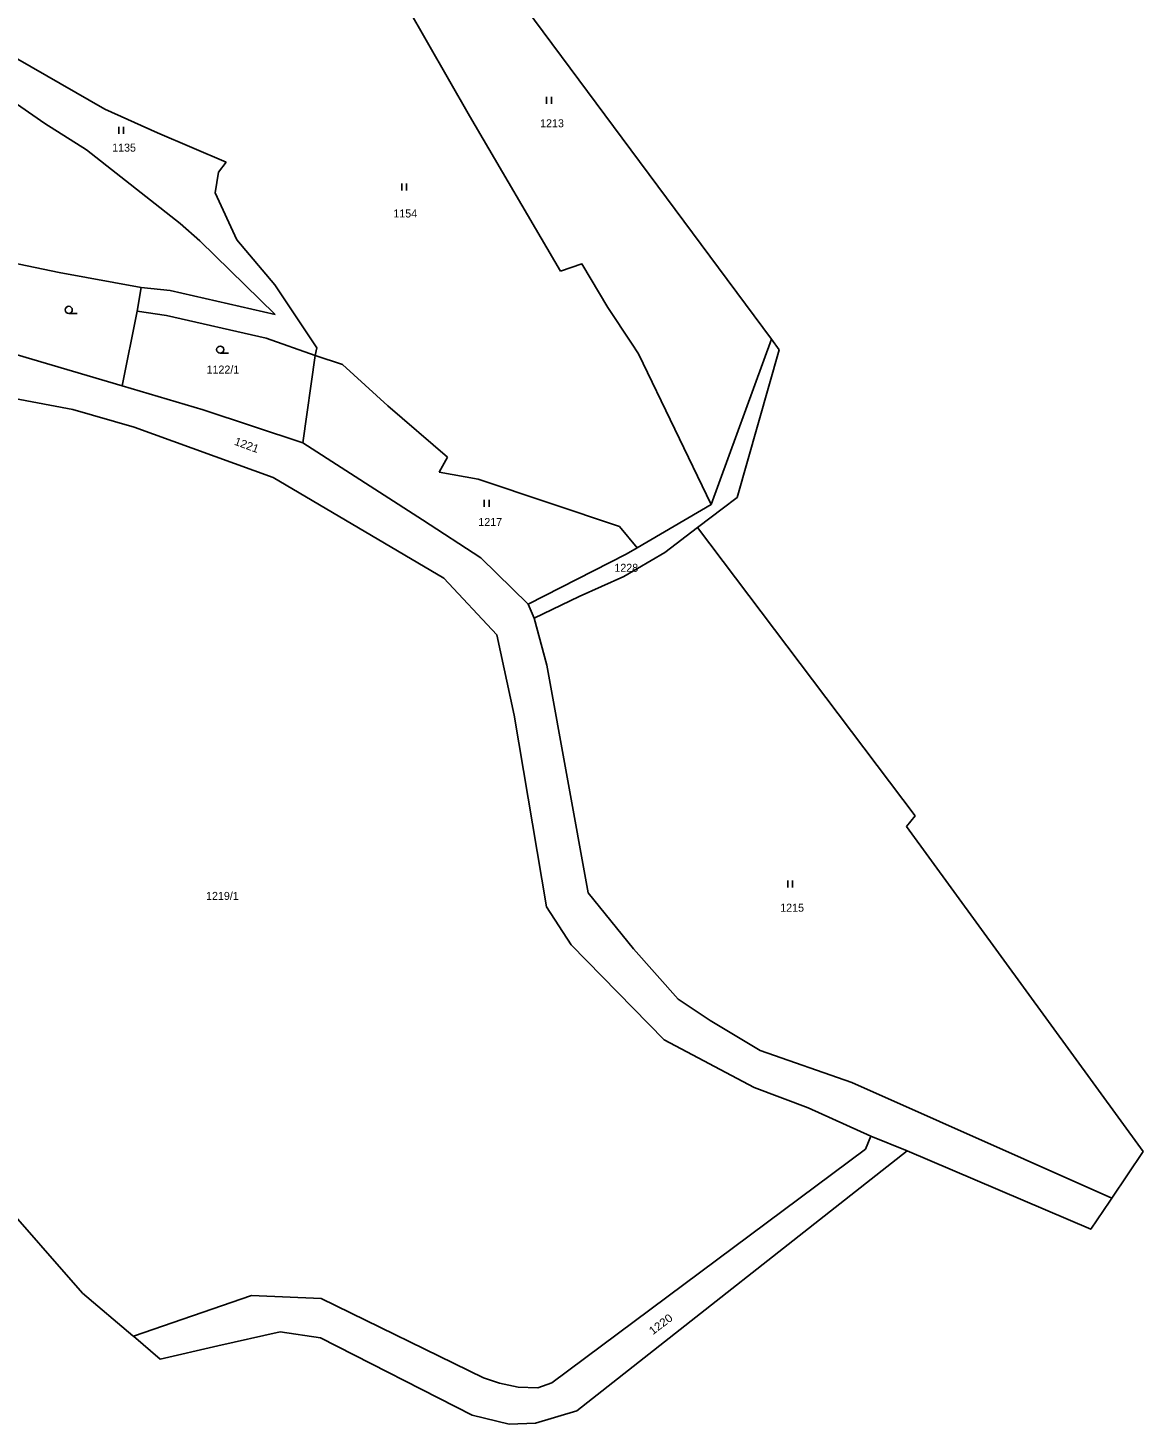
# Model space of a CAD drawing. Extents: x -744132 to -742433, y -984679 to -982287.
# Drawn here: x -742676.3 to -742439.3, y -983667 to -983370.4 of the extents above; entities that cross this region are included whole.
import ezdxf

# ---------------------------------------------------------------- set-up
doc = ezdxf.new("R2010")
doc.units = 0
doc.header["$LTSCALE"] = 0.68
doc.layers.add('1', color=7, linetype='Continuous', lineweight=25)
doc.layers.add('3', color=7, linetype='Continuous', lineweight=25)
doc.layers.add('2', color=7, linetype='Continuous')

msp = doc.modelspace()

# ---------------------------------------------------------------- linework, layer by layer
at = {"layer": '1'}
for p, q in [((-742608.33, -983315.24), (-742518.29, -983436.49)), ((-742595.81, -983365.68), (-742582.42, -983389.06)), ((-742681.79, -983375.07), (-742659.97, -983387.64)), ((-742672.71, -983390.65), (-742685.29, -983381.98)), ((-742659.97, -983387.64), (-742648.78, -983392.66)), ((-742582.42, -983389.06), (-742563.1, -983422.03)), ((-742663.86, -983396.26), (-742672.71, -983390.65)), ((-742648.78, -983392.66), (-742634.19, -983398.9)), ((-742643.96, -983411.94), (-742663.86, -983396.26)), ((-742634.19, -983398.9), (-742635.79, -983401.01)), ((-742635.79, -983401.01), (-742636.53, -983405.38)), ((-742636.53, -983405.38), (-742631.9, -983415.37)), ((-742639.78, -983415.64), (-742643.96, -983411.94)), ((-742623.76, -983431.28), (-742639.78, -983415.64)), ((-742631.9, -983415.37), (-742623.82, -983424.93)), ((-742681.58, -983419.83), (-742669.64, -983422.3)), ((-742669.64, -983422.3), (-742652.21, -983425.49)), ((-742652.21, -983425.49), (-742653.11, -983430.52)), ((-742652.21, -983425.49), (-742646.08, -983426.16)), ((-742646.08, -983426.16), (-742623.76, -983431.28)), ((-742623.82, -983424.93), (-742614.89, -983438.36)), ((-742653.11, -983430.52), (-742656.23, -983446.44)), ((-742653.11, -983430.52), (-742646.86, -983431.45)), ((-742553.08, -983429.77), (-742547.99, -983437.34)), ((-742646.86, -983431.45), (-742625.64, -983436.29)), ((-742625.64, -983436.29), (-742615.23, -983439.97)), ((-742531.12, -983471.6), (-742518.29, -983436.49)), ((-742516.61, -983438.75), (-742518.29, -983436.49)), ((-742683.09, -983438.48), (-742656.23, -983446.44)), ((-742614.89, -983438.36), (-742615.23, -983439.97)), ((-742547.99, -983437.34), (-742546.5, -983439.63)), ((-742525.53, -983470.1), (-742516.61, -983438.75)), ((-742617.9, -983458.53), (-742615.23, -983439.97)), ((-742615.23, -983439.97), (-742609.46, -983441.91)), ((-742609.46, -983441.91), (-742599.78, -983450.64)), ((-742546.5, -983439.63), (-742531.12, -983471.6)), ((-742691.68, -983446.7), (-742666.78, -983451.42)), ((-742656.23, -983446.44), (-742639.05, -983451.53)), ((-742599.78, -983450.64), (-742587.15, -983461.56)), ((-742666.78, -983451.42), (-742653.68, -983455.2)), ((-742639.05, -983451.53), (-742617.9, -983458.53)), ((-742653.68, -983455.2), (-742624.17, -983465.85)), ((-742592.46, -983474.85), (-742617.9, -983458.53)), ((-742587.15, -983461.56), (-742588.88, -983464.78)), ((-742624.17, -983465.85), (-742587.88, -983487.3)), ((-742588.88, -983464.78), (-742580.58, -983466.26)), ((-742580.58, -983466.26), (-742550.54, -983476.31)), ((-742531.12, -983471.6), (-742546.84, -983480.82)), ((-742528.73, -983472.52), (-742525.53, -983470.1)), ((-742580.04, -983482.94), (-742592.46, -983474.85)), ((-742533.98, -983476.47), (-742531.09, -983474.3)), ((-742531.09, -983474.3), (-742528.73, -983472.52)), ((-742550.54, -983476.31), (-742546.84, -983480.82)), ((-742533.98, -983476.47), (-742540.94, -983481.8)), ((-742487.72, -983537.78), (-742533.98, -983476.47)), ((-742549.18, -983482.19), (-742546.84, -983480.82)), ((-742569.98, -983492.78), (-742580.04, -983482.94)), ((-742569.98, -983492.78), (-742549.18, -983482.19)), ((-742540.94, -983481.8), (-742549.63, -983486.9)), ((-742549.63, -983486.9), (-742559.16, -983491.17)), ((-742587.88, -983487.3), (-742576.67, -983499.31)), ((-742569.98, -983492.78), (-742568.72, -983495.73)), ((-742559.16, -983491.17), (-742568.72, -983495.73)), ((-742568.72, -983495.73), (-742566.03, -983505.75)), ((-742576.67, -983499.31), (-742572.94, -983516.35)), ((-742566.03, -983505.75), (-742557.22, -983554.09)), ((-742572.94, -983516.35), (-742566.11, -983557.08)), ((-742489.59, -983540.03), (-742487.72, -983537.78)), ((-742439.29, -983609.05), (-742489.59, -983540.03)), ((-742557.22, -983554.09), (-742547.59, -983566.02)), ((-742566.11, -983557.08), (-742560.83, -983565.19)), ((-742560.83, -983565.19), (-742541.06, -983585.33)), ((-742547.59, -983566.02), (-742538.13, -983576.67)), ((-742538.13, -983576.67), (-742531.3, -983581.22)), ((-742531.3, -983581.22), (-742520.65, -983587.59)), ((-742541.06, -983585.33), (-742521.97, -983595.45)), ((-742520.65, -983587.59), (-742501.17, -983594.4)), ((-742521.97, -983595.45), (-742510.46, -983599.79)), ((-742501.17, -983594.4), (-742445.96, -983618.96)), ((-742510.46, -983599.79), (-742497.18, -983605.81)), ((-742498.32, -983608.54), (-742564.93, -983658.21)), ((-742497.18, -983605.81), (-742498.32, -983608.54)), ((-742497.18, -983605.81), (-742489.43, -983608.94)), ((-742559.66, -983664.16), (-742489.43, -983608.94)), ((-742445.96, -983618.96), (-742439.29, -983609.05)), ((-742683.1, -983618.19), (-742664.68, -983639.13)), ((-742446.38, -983619.59), (-742445.96, -983618.96)), ((-742664.68, -983639.13), (-742653.97, -983648.22)), ((-742628.75, -983639.68), (-742653.84, -983648.33)), ((-742614, -983640.27), (-742628.75, -983639.68)), ((-742579.44, -983657.18), (-742614, -983640.27)), ((-742653.97, -983648.22), (-742653.84, -983648.33)), ((-742653.84, -983648.33), (-742648.16, -983653.15)), ((-742635.96, -983650.35), (-742622.71, -983647.35)), ((-742622.71, -983647.35), (-742614.13, -983648.66)), ((-742614.13, -983648.66), (-742581.87, -983665.1)), ((-742648.16, -983653.15), (-742635.96, -983650.35)), ((-742576.06, -983658.3), (-742579.44, -983657.18)), ((-742572.07, -983659.12), (-742576.06, -983658.3)), ((-742564.93, -983658.21), (-742567.95, -983659.3)), ((-742567.95, -983659.3), (-742572.07, -983659.12)), ((-742568.43, -983666.78), (-742559.66, -983664.16)), ((-742581.87, -983665.1), (-742574.03, -983666.97)), ((-742574.03, -983666.97), (-742568.43, -983666.78))]:
    msp.add_line(p, q, dxfattribs=at)
for points in [[(-742563.1, -983422.03), (-742558.57, -983420.5), (-742553.08, -983429.77)], [(-742489.43, -983608.94), (-742450.42, -983625.59), (-742446.38, -983619.59)]]:
    msp.add_lwpolyline(points, dxfattribs=at)
at = {"layer": '3'}
for p, q in [((-742566.051, -983386.51), (-742566.051, -983385.01)), ((-742565.05, -983386.51), (-742565.05, -983385.01)), ((-742656.961, -983392.89), (-742656.961, -983391.39)), ((-742655.96, -983392.89), (-742655.96, -983391.39)), ((-742596.861, -983404.94), (-742596.861, -983403.44)), ((-742595.86, -983404.94), (-742595.86, -983403.44)), ((-742667.613, -983431.02), (-742665.863, -983431.02)), ((-742635.433, -983439.47), (-742633.683, -983439.47)), ((-742579.301, -983472.1), (-742579.301, -983470.6)), ((-742578.3, -983472.1), (-742578.3, -983470.6)), ((-742514.821, -983552.98), (-742514.821, -983551.48)), ((-742513.82, -983552.98), (-742513.82, -983551.48))]:
    msp.add_line(p, q, dxfattribs=at)
for centre in [(-742667.6129, -983430.2698), (-742635.4329, -983438.7198)]:
    msp.add_circle(centre, 0.75, dxfattribs=at)

# ---------------------------------------------------------------- texts
at = {"layer": '2'}
for s, p in [('1213', (-742567.44, -983391.485)), ('1135', (-742658.39, -983396.655)), ('1154', (-742598.63, -983410.645)), ('1122/1', (-742638.33, -983443.805)), ('1217', (-742580.57, -983476.185)), ('1228', (-742551.66, -983485.915)), ('1219/1', (-742638.44, -983555.615)), ('1215', (-742516.41, -983558.125))]:
    msp.add_text(s, height=1.7, dxfattribs=at).set_placement(p)
for s, rotation, width, p in [('1221', 340, 1.05, (-742632.575, -983458.879)), ('1220', 37, 1.1, (-742543.514, -983648.109))]:
    msp.add_text(s, height=1.7, rotation=rotation, dxfattribs=dict(at, width=width)).set_placement(p)

doc.saveas('drawing.dxf')
